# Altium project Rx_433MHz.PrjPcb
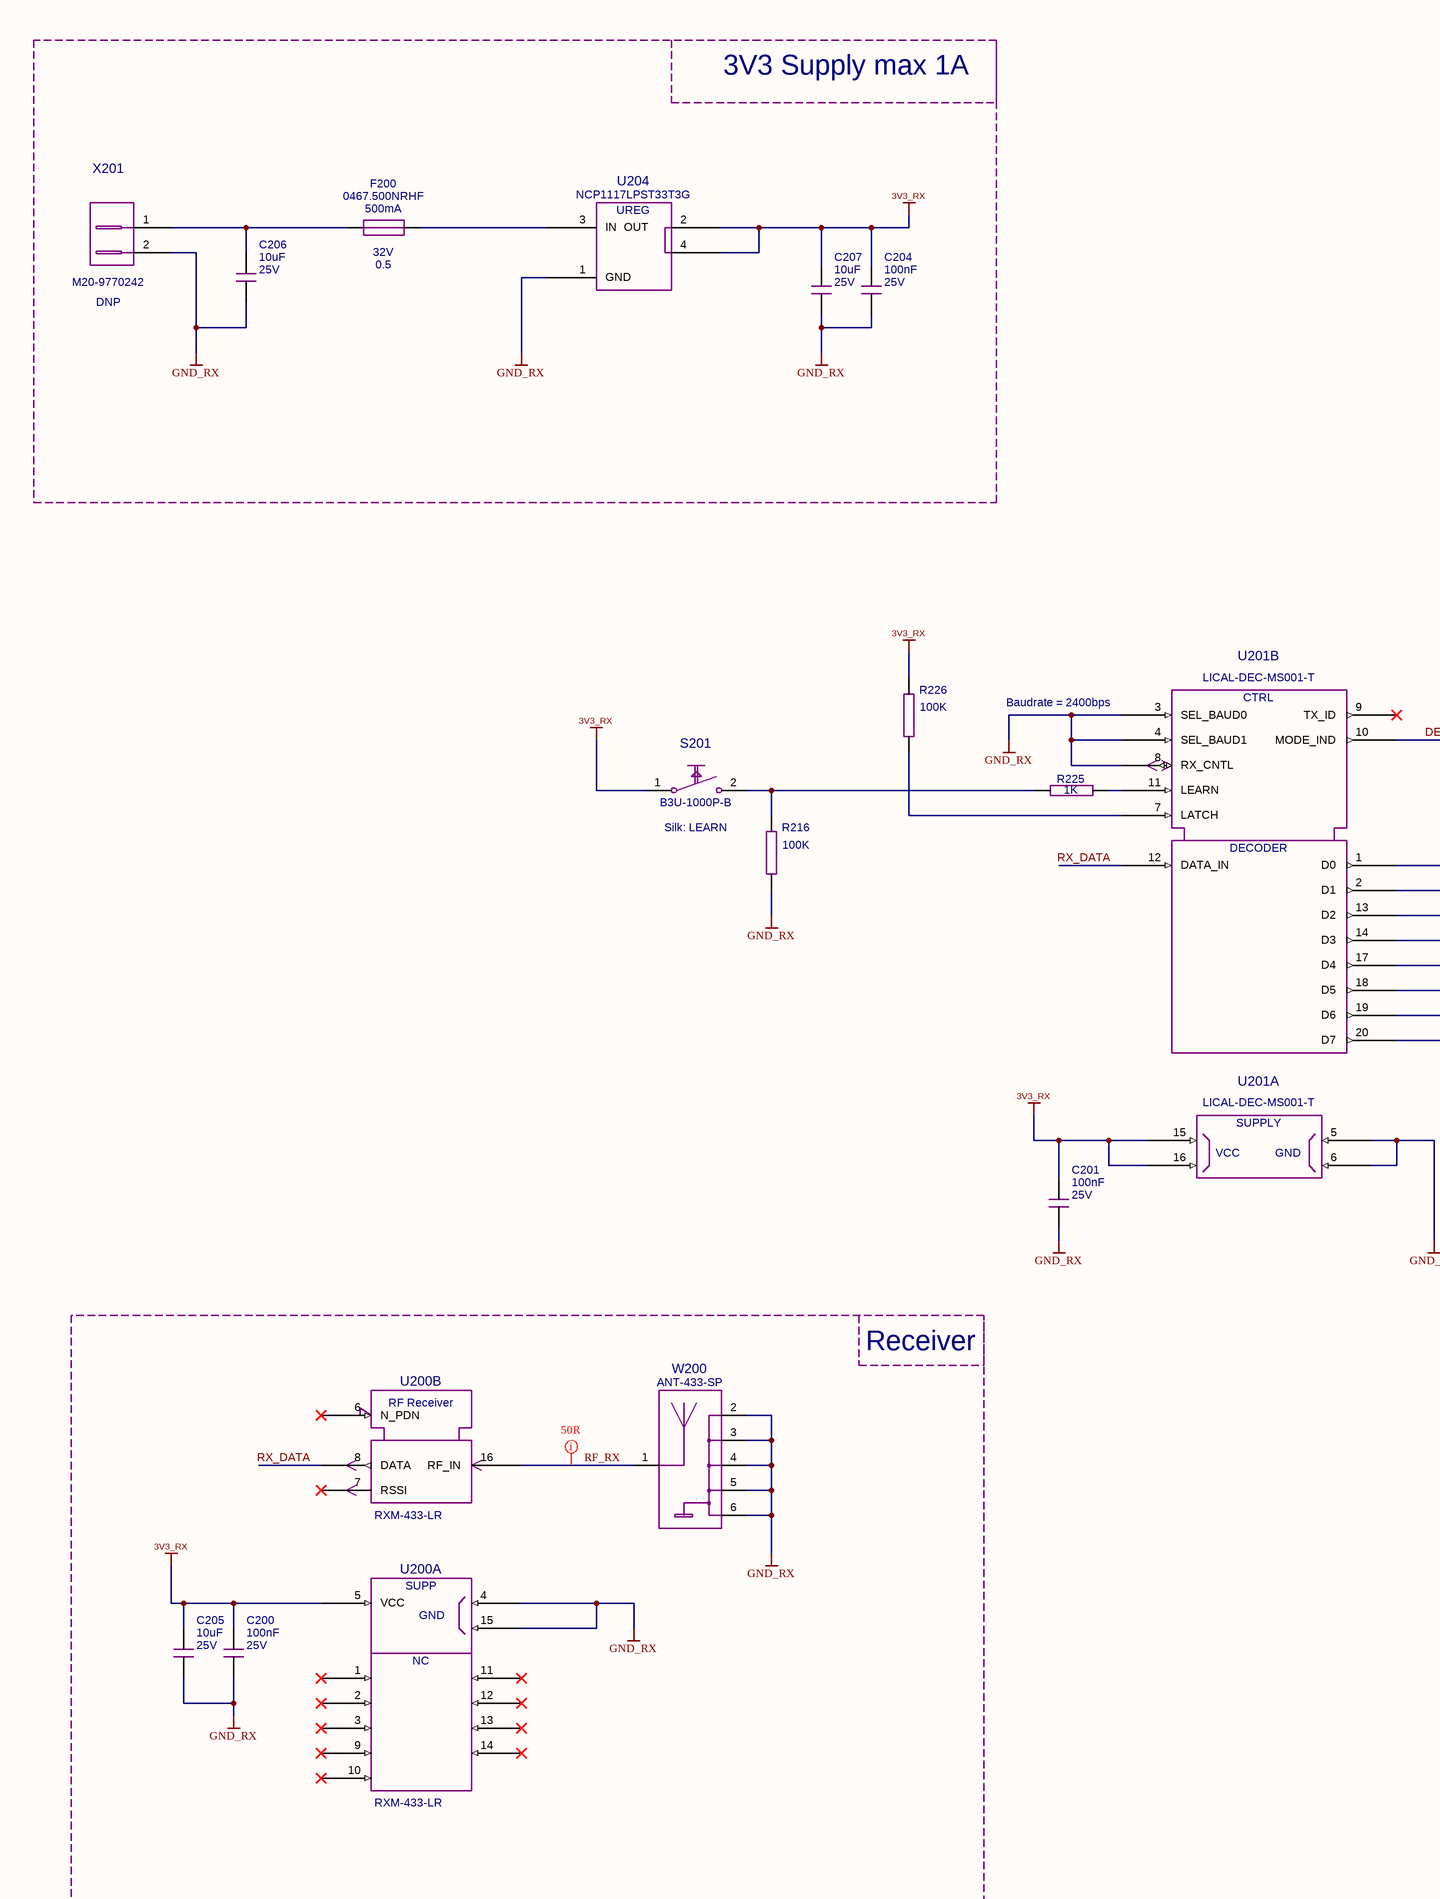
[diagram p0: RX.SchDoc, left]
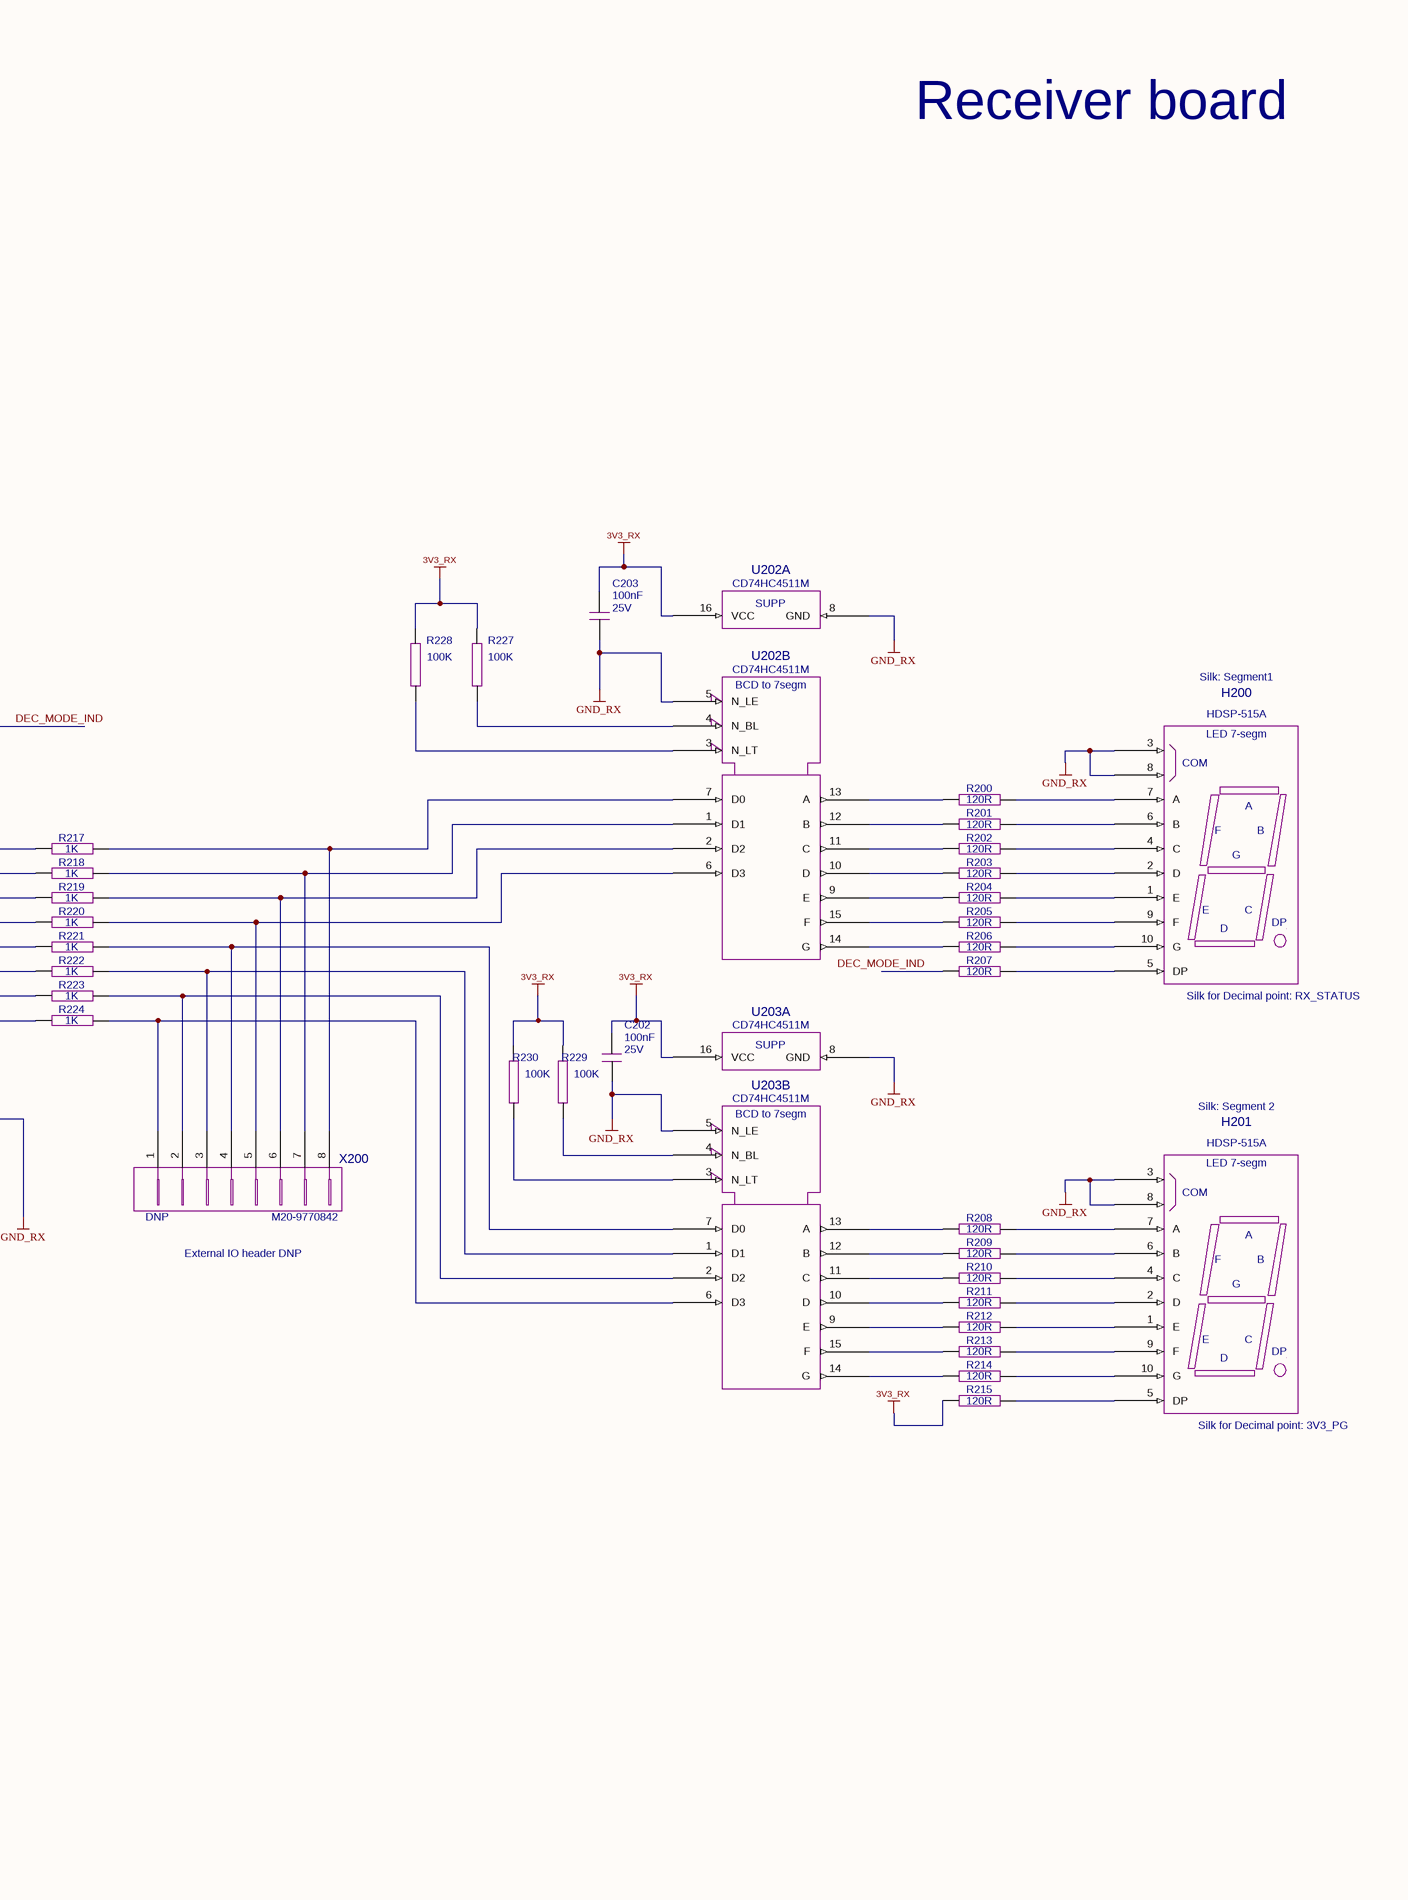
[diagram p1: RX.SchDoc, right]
1 sheet, 51 parts. Net scope: hierarchical (ports join the sheet entries above them; power ports are global).
Board files: Rx_433MHz.PcbDoc, Rx_433MHz-Placed.PcbDoc, Rx_433MHz-Routed.PcbDoc

## Sheet RX.SchDoc
size 594 x 420 mm; APPROVED: Yes; Border_Classification: ?; CmpIndex: 0; ENGINEER: KuRe/SnLe; REVIEWED: Yes; REVISION: 2.0; SymIndex: 1

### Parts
C200  value 100nF  Voltage: 25V  [CAPC1608X90N_0603_GENERIC]  (hidden comment: C_0603_1608X90_GENERIC)
C201  value 100nF  Voltage: 25V  [CAPC1608X90N_0603_GENERIC]  (hidden comment: C_0603_1608X90_GENERIC)
C202  value 100nF  Voltage: 25V  [CAPC1608X90N_0603_GENERIC]  (hidden comment: C_0603_1608X90_GENERIC)
C203  value 100nF  Voltage: 25V  [CAPC1608X90N_0603_GENERIC]  (hidden comment: C_0603_1608X90_GENERIC)
C204  value 100nF  Voltage: 25V  [CAPC1608X90N_0603_GENERIC]  (hidden comment: C_0603_1608X90_GENERIC)
C205  value 10uF  Voltage: 25V  [CAPC3216X190N_1206_GENERIC]  (hidden comment: C_1206_3216X190_GENERIC)
C206  value 10uF  Voltage: 25V  [CAPC2013X140N_AVX]  (hidden comment: 08051C104KAZ2A)
C207  value 10uF  Voltage: 25V  [CAPC2013X140N_AVX]  (hidden comment: 08051C104KAZ2A)
F200  value 500mA  Current: 0.5  MPN: 0467.500NRHF  Voltage: 32V  [RESC1608X60N_0603_GENERIC]  (hidden comment: 0467XXXX)
H200  MPN: HDSP-515A  [BROADCOM_HDSP-5XXX]  (hidden comment: HDSP-5XXX)
H201  MPN: HDSP-515A  [BROADCOM_HDSP-5XXX]  (hidden comment: HDSP-5XXX)
R200  value 120R  [RESC2012X60N_0805_GENERIC]  (hidden comment: R_0805_2012X60_GENERIC)
R201  value 120R  [RESC2012X60N_0805_GENERIC]  (hidden comment: R_0805_2012X60_GENERIC)
R202  value 120R  [RESC2012X60N_0805_GENERIC]  (hidden comment: R_0805_2012X60_GENERIC)
R203  value 120R  [RESC2012X60N_0805_GENERIC]  (hidden comment: R_0805_2012X60_GENERIC)
R204  value 120R  [RESC2012X60N_0805_GENERIC]  (hidden comment: R_0805_2012X60_GENERIC)
R205  value 120R  [RESC2012X60N_0805_GENERIC]  (hidden comment: R_0805_2012X60_GENERIC)
R206  value 120R  [RESC2012X60N_0805_GENERIC]  (hidden comment: R_0805_2012X60_GENERIC)
R207  value 120R  [RESC2012X60N_0805_GENERIC]  (hidden comment: R_0805_2012X60_GENERIC)
R208  value 120R  [RESC2012X60N_0805_GENERIC]  (hidden comment: R_0805_2012X60_GENERIC)
R209  value 120R  [RESC2012X60N_0805_GENERIC]  (hidden comment: R_0805_2012X60_GENERIC)
R210  value 120R  [RESC2012X60N_0805_GENERIC]  (hidden comment: R_0805_2012X60_GENERIC)
R211  value 120R  [RESC2012X60N_0805_GENERIC]  (hidden comment: R_0805_2012X60_GENERIC)
R212  value 120R  [RESC2012X60N_0805_GENERIC]  (hidden comment: R_0805_2012X60_GENERIC)
R213  value 120R  [RESC2012X60N_0805_GENERIC]  (hidden comment: R_0805_2012X60_GENERIC)
R214  value 120R  [RESC2012X60N_0805_GENERIC]  (hidden comment: R_0805_2012X60_GENERIC)
R215  value 120R  [RESC2012X60N_0805_GENERIC]  (hidden comment: R_0805_2012X60_GENERIC)
R216  value 100K  [RESC2012X60N_0805_GENERIC]  (hidden comment: R_0805_2012X60_GENERIC)
R217  value 1K  [RESC2012X60N_0805_GENERIC]  (hidden comment: R_0805_2012X60_GENERIC)
R218  value 1K  [RESC2012X60N_0805_GENERIC]  (hidden comment: R_0805_2012X60_GENERIC)
R219  value 1K  [RESC2012X60N_0805_GENERIC]  (hidden comment: R_0805_2012X60_GENERIC)
R220  value 1K  [RESC2012X60N_0805_GENERIC]  (hidden comment: R_0805_2012X60_GENERIC)
R221  value 1K  [RESC2012X60N_0805_GENERIC]  (hidden comment: R_0805_2012X60_GENERIC)
R222  value 1K  [RESC2012X60N_0805_GENERIC]  (hidden comment: R_0805_2012X60_GENERIC)
R223  value 1K  [RESC2012X60N_0805_GENERIC]  (hidden comment: R_0805_2012X60_GENERIC)
R224  value 1K  [RESC2012X60N_0805_GENERIC]  (hidden comment: R_0805_2012X60_GENERIC)
R225  value 1K  [RESC2012X60N_0805_GENERIC]  (hidden comment: R_0805_2012X60_GENERIC)
R226  value 100K  [RESC2012X60N_0805_GENERIC]  (hidden comment: R_0805_2012X60_GENERIC)
R227  value 100K  [RESC2012X60N_0805_GENERIC]  (hidden comment: R_0805_2012X60_GENERIC)
R228  value 100K  [RESC2012X60N_0805_GENERIC]  (hidden comment: R_0805_2012X60_GENERIC)
R229  value 100K  [RESC2012X60N_0805_GENERIC]  (hidden comment: R_0805_2012X60_GENERIC)
R230  value 100K  [RESC2012X60N_0805_GENERIC]  (hidden comment: R_0805_2012X60_GENERIC)
S201  MPN: B3U-1000P-B  [OMRON_B3U_1000P_B]  (hidden comment: B3U_1000P_B)
U200  RXM-433-LR  [LINX_RXM-433-LR]  (parts A,B of 2)
U201  MPN: LICAL-DEC-MS001-T  [SOP65P780X200-20N]  (hidden comment: LICAL-DEC-MS001)  (parts A,B of 2)
U202  CD74HC4511M  [SOIC127P600X175-16N]  (parts A,B of 2)
U203  CD74HC4511M  [SOIC127P600X175-16N]  (parts A,B of 2)
U204  MPN: NCP1117LPST33T3G  [SOT230P700X180-4N]  (hidden comment: LM1117MPX)
W200  ANT-433-SP  [LINX_ANT-433-SP]
X200  MPN: M20-9770842  Place: DNP  [HARWIN_M20_9770842]  (hidden comment: M20_9770842)
X201  MPN: M20-9770242  Place: DNP  [HARWIN_M20_9770242]  (hidden comment: M20_9770242)

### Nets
3V3_RX: C200.1(P) C201.1(P) C202.1(P) C203.1(P) C204.1(P) C205.1(P) C207.1(P) R215.1(P) R226.2(M) R227.2(M) R228.2(M) R229.2(M) R230.2(M) S201.1(S1) U200.5(VCC) U201.15(VCC1) U201.16(VCC2) U202.16(VCC) U203.16(VCC) U204.2(OUT) U204.4(TAB)
GND_RX: C200.2(M) C201.2(M) C202.2(M) C203.2(M) C204.2(M) C205.2(M) C206.2(M) C207.2(M) H200.3(COM1) H200.8(COM2) H201.3(COM1) H201.8(COM2) R216.1(P) U200.4(GND1) U200.15(GND2) U201.3(SEL_BAUD0) U201.4(SEL_BAUD1) U201.5(GND1) U201.6(GND2) U201.8(RX_CNTL) U202.5(N_LE) U202.8(GND) U203.5(N_LE) U203.8(GND) U204.1(GND) W200.2(GND1) W200.3(GND2) W200.4(GND3) W200.5(GND4) W200.6(GND5) X201.2(P2)
DEC_MODE_IND: R207.1(P) U201.10(MODE_IND)
RF_RX: U200.16(RF_IN) W200.1(ANT)
RX_DATA: U200.8(DATA) U201.12(DATA_IN)
NetC206_1: C206.1(P) F200.1(A) X201.1(P1)
NetF200_2: F200.2(B) U204.3(IN)
NetH200_1: H200.1(E) R204.2(M)
NetH200_2: H200.2(D) R203.2(M)
NetH200_4: H200.4(C) R202.2(M)
NetH200_5: H200.5(DP) R207.2(M)
NetH200_6: H200.6(B) R201.2(M)
NetH200_7: H200.7(A) R200.2(M)
NetH200_9: H200.9(F) R205.2(M)
NetH200_10: H200.10(G) R206.2(M)
NetH201_1: H201.1(E) R212.2(M)
NetH201_2: H201.2(D) R211.2(M)
NetH201_4: H201.4(C) R210.2(M)
NetH201_5: H201.5(DP) R215.2(M)
NetH201_6: H201.6(B) R209.2(M)
NetH201_7: H201.7(A) R208.2(M)
NetH201_9: H201.9(F) R213.2(M)
NetH201_10: H201.10(G) R214.2(M)
NetR200_1: R200.1(P) U202.13(A)
NetR201_1: R201.1(P) U202.12(B)
NetR202_1: R202.1(P) U202.11(C)
NetR203_1: R203.1(P) U202.10(D)
NetR204_1: R204.1(P) U202.9(E)
NetR205_1: R205.1(P) U202.15(F)
NetR206_1: R206.1(P) U202.14(G)
NetR208_1: R208.1(P) U203.13(A)
NetR209_1: R209.1(P) U203.12(B)
NetR210_1: R210.1(P) U203.11(C)
NetR211_1: R211.1(P) U203.10(D)
NetR212_1: R212.1(P) U203.9(E)
NetR213_1: R213.1(P) U203.15(F)
NetR214_1: R214.1(P) U203.14(G)
NetR216_2: R216.2(M) R225.1(P) S201.2(S2)
NetR217_1: R217.1(P) U201.1(D0)
NetR217_2: R217.2(M) U202.7(D0) X200.8(P8)
NetR218_1: R218.1(P) U201.2(D1)
NetR218_2: R218.2(M) U202.1(D1) X200.7(P7)
NetR219_1: R219.1(P) U201.13(D2)
NetR219_2: R219.2(M) U202.2(D2) X200.6(P6)
NetR220_1: R220.1(P) U201.14(D3)
NetR220_2: R220.2(M) U202.6(D3) X200.5(P5)
NetR221_1: R221.1(P) U201.17(D4)
NetR221_2: R221.2(M) U203.7(D0) X200.4(P4)
NetR222_1: R222.1(P) U201.18(D5)
NetR222_2: R222.2(M) U203.1(D1) X200.3(P3)
NetR223_1: R223.1(P) U201.19(D6)
NetR223_2: R223.2(M) U203.2(D2) X200.2(P2)
NetR224_1: R224.1(P) U201.20(D7)
NetR224_2: R224.2(M) U203.6(D3) X200.1(P1)
NetR225_2: R225.2(M) U201.11(LEARN)
NetR226_1: R226.1(P) U201.7(LATCH)
NetR227_1: R227.1(P) U202.4(N_BL)
NetR228_1: R228.1(P) U202.3(N_LT)
NetR229_1: R229.1(P) U203.4(N_BL)
NetR230_1: R230.1(P) U203.3(N_LT)

Not connected (* = marked no-connect by the designer): U200 1(NC1)* 2(NC2)* 3(NC3)* 6(N_PDN)* 7(RSSI)* 9(NC4)* 10(NC5)* 11(NC6)* 12(NC7)* 13(NC8)* 14(NC9)*; U201 9(TX_ID)*

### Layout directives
net class 50R: RF_RX

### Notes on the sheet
- 3V3 Supply max 1A
- Receiver board
- Baudrate = 2400bps
- Silk: Segment1
- Silk: LEARN
- (near H200) Silk for Decimal point: RX_STATUS
- Silk: Segment 2
- External IO header DNP
- Receiver
- (near H201) Silk for Decimal point: 3V3_PG

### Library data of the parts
C200 = C_0603_1608X90_GENERIC: 100nF 25V 10%; Manufacturer: MURATA; MPN: GRM188R71E104KA01D; Part Name: Ceramic chip capacitor 0603-1608x90, generic; Parts: 1; Capacitance: 100000; CmpIndex: 30; Dielectric: X7R; DXDB_LIBNAME: Capacitor; Level: STD; Ref Designator: C200; SymIndex: 23; Tolerance: 10; Type: Ceramic; Valid: -1
C201 = C_0603_1608X90_GENERIC: 100nF 25V 10%; Manufacturer: MURATA; MPN: GRM188R71E104KA01D; Part Name: Ceramic chip capacitor 0603-1608x90, generic; Parts: 1; Capacitance: 100000; CmpIndex: 52; Dielectric: X7R; DXDB_LIBNAME: Capacitor; Level: STD; Ref Designator: C201; SymIndex: 23; Tolerance: 10; Type: Ceramic; Valid: -1
C202 = C_0603_1608X90_GENERIC: 100nF 25V 10%; Manufacturer: MURATA; MPN: GRM188R71E104KA01D; Part Name: Ceramic chip capacitor 0603-1608x90, generic; Parts: 1; Capacitance: 100000; CmpIndex: 80; Dielectric: X7R; DXDB_LIBNAME: Capacitor; Level: STD; Ref Designator: C202; SymIndex: 23; Tolerance: 10; Type: Ceramic; Valid: -1
C203 = C_0603_1608X90_GENERIC: 100nF 25V 10%; Manufacturer: MURATA; MPN: GRM188R71E104KA01D; Part Name: Ceramic chip capacitor 0603-1608x90, generic; Parts: 1; Capacitance: 100000; CmpIndex: 81; Dielectric: X7R; DXDB_LIBNAME: Capacitor; Level: STD; Ref Designator: C203; SymIndex: 23; Tolerance: 10; Type: Ceramic; Valid: -1
C204 = C_0603_1608X90_GENERIC: 100nF 25V 10%; Manufacturer: MURATA; MPN: GRM188R71E104KA01D; Part Name: Ceramic chip capacitor 0603-1608x90, generic; Parts: 1; Capacitance: 100000; CmpIndex: 16; Dielectric: X7R; DXDB_LIBNAME: Capacitor; Level: STD; Ref Designator: C204; SymIndex: 23; Tolerance: 10; Type: Ceramic; Valid: -1
C205 = C_1206_3216X190_GENERIC: 10uF 25V 10%; Manufacturer: AVX; MPN: 12063C106KAT2A; Part Name: Cheramic chip capacitor 1206-3216x190, generic; Parts: 1; Capacitance: 10000000; CmpIndex: 33; Dielectric: X7R; DXDB_LIBNAME: Capacitor; Level: STD; Max Temp: +125; Min Temp: -55; Ref Designator: C205; SymIndex: 23; Tolerance: 10; Type: Ceramic; Valid: -1
C206 = 08051C104KAZ2A: 10uF 25V 10%; Manufacturer: AVX; MPN: 08053D106KAT2A; Part Name: 0805 chip 100nF 10% 100V X7R; Parts: 1; Capacitance: 10000000; CmpIndex: 12; Dielectric: X5R; DXDB_LIBNAME: Capacitor; Level: STD; Ref Designator: C206; SymIndex: 23; Tolerance: 10; Type: Ceramic; Valid: 0
C207 = 08051C104KAZ2A: 10uF 25V 10%; Manufacturer: AVX; MPN: 08053D106KAT2A; Part Name: 0805 chip 100nF 10% 100V X7R; Parts: 1; Capacitance: 10000000; CmpIndex: 15; Dielectric: X5R; DXDB_LIBNAME: Capacitor; Level: STD; Ref Designator: C207; SymIndex: 23; Tolerance: 10; Type: Ceramic; Valid: 0
F200 = 0467XXXX: Thin film 0603 fuse very fast acting; Manufacturer: LITTELFUSE; Part Name: Thin film 0603 very fast acting; CmpIndex: 18; Level: STD; Max Temp: +90; Min Temp: -55; Ref Designator: F200; SymIndex: 25; Valid: -1
H200 = HDSP-5XXX: 7 Segment Display Module Red, 1,85V, 20mA. THT; Manufacturer: BROADCOM; Part Name: Single Digit LED Numeric Display, Blue color; CmpIndex: 5; DXDB_LIBNAME: Optical; Level: STD; Max Temp: 85; Min Temp: -25; Ref Designator: H200; SymIndex: 14; Valid: 0
H201 = HDSP-5XXX: 7 Segment Display Module Red, 1,85V, 20mA. THT; Manufacturer: BROADCOM; Part Name: Single Digit LED Numeric Display, Blue color; CmpIndex: 66; DXDB_LIBNAME: Optical; Level: STD; Max Temp: 85; Min Temp: -25; Ref Designator: H201; SymIndex: 14; Valid: 0
R200 = R_0805_2012X60_GENERIC: 0.125W 5% 120R 50V; Manufacturer: YAGEO; MPN: RC0805JR-07120RL; Part Name: resistor_0805-2012x60 generic; CmpIndex: 40; DXDB_LIBNAME: Resistor_0805; Level: STD; Ref Designator: R200; SymIndex: 28; Valid: -1
R201 = R_0805_2012X60_GENERIC: 0.125W 5% 120R 50V; Manufacturer: YAGEO; MPN: RC0805JR-07120RL; Part Name: resistor_0805-2012x60 generic; CmpIndex: 41; DXDB_LIBNAME: Resistor_0805; Level: STD; Ref Designator: R201; SymIndex: 28; Valid: -1
R202 = R_0805_2012X60_GENERIC: 0.125W 5% 120R 50V; Manufacturer: YAGEO; MPN: RC0805JR-07120RL; Part Name: resistor_0805-2012x60 generic; CmpIndex: 60; DXDB_LIBNAME: Resistor_0805; Level: STD; Ref Designator: R202; SymIndex: 28; Valid: -1
R203 = R_0805_2012X60_GENERIC: 0.125W 5% 120R 50V; Manufacturer: YAGEO; MPN: RC0805JR-07120RL; Part Name: resistor_0805-2012x60 generic; CmpIndex: 61; DXDB_LIBNAME: Resistor_0805; Level: STD; Ref Designator: R203; SymIndex: 28; Valid: -1
R204 = R_0805_2012X60_GENERIC: 0.125W 5% 120R 50V; Manufacturer: YAGEO; MPN: RC0805JR-07120RL; Part Name: resistor_0805-2012x60 generic; CmpIndex: 62; DXDB_LIBNAME: Resistor_0805; Level: STD; Ref Designator: R204; SymIndex: 28; Valid: -1
R205 = R_0805_2012X60_GENERIC: 0.125W 5% 120R 50V; Manufacturer: YAGEO; MPN: RC0805JR-07120RL; Part Name: resistor_0805-2012x60 generic; CmpIndex: 63; DXDB_LIBNAME: Resistor_0805; Level: STD; Ref Designator: R205; SymIndex: 28; Valid: -1
R206 = R_0805_2012X60_GENERIC: 0.125W 5% 120R 50V; Manufacturer: YAGEO; MPN: RC0805JR-07120RL; Part Name: resistor_0805-2012x60 generic; CmpIndex: 64; DXDB_LIBNAME: Resistor_0805; Level: STD; Ref Designator: R206; SymIndex: 28; Valid: -1
R207 = R_0805_2012X60_GENERIC: 0.125W 5% 120R 50V; Manufacturer: YAGEO; MPN: RC0805JR-07120RL; Part Name: resistor_0805-2012x60 generic; CmpIndex: 73; DXDB_LIBNAME: Resistor_0805; Level: STD; Ref Designator: R207; SymIndex: 28; Valid: -1
R208 = R_0805_2012X60_GENERIC: 0.125W 5% 120R 50V; Manufacturer: YAGEO; MPN: RC0805JR-07120RL; Part Name: resistor_0805-2012x60 generic; CmpIndex: 6; DXDB_LIBNAME: Resistor_0805; Level: STD; Ref Designator: R208; SymIndex: 28; Valid: -1
R209 = R_0805_2012X60_GENERIC: 0.125W 5% 120R 50V; Manufacturer: YAGEO; MPN: RC0805JR-07120RL; Part Name: resistor_0805-2012x60 generic; CmpIndex: 67; DXDB_LIBNAME: Resistor_0805; Level: STD; Ref Designator: R209; SymIndex: 28; Valid: -1
R210 = R_0805_2012X60_GENERIC: 0.125W 5% 120R 50V; Manufacturer: YAGEO; MPN: RC0805JR-07120RL; Part Name: resistor_0805-2012x60 generic; CmpIndex: 68; DXDB_LIBNAME: Resistor_0805; Level: STD; Ref Designator: R210; SymIndex: 28; Valid: -1
R211 = R_0805_2012X60_GENERIC: 0.125W 5% 120R 50V; Manufacturer: YAGEO; MPN: RC0805JR-07120RL; Part Name: resistor_0805-2012x60 generic; CmpIndex: 69; DXDB_LIBNAME: Resistor_0805; Level: STD; Ref Designator: R211; SymIndex: 28; Valid: -1
R212 = R_0805_2012X60_GENERIC: 0.125W 5% 120R 50V; Manufacturer: YAGEO; MPN: RC0805JR-07120RL; Part Name: resistor_0805-2012x60 generic; CmpIndex: 70; DXDB_LIBNAME: Resistor_0805; Level: STD; Ref Designator: R212; SymIndex: 28; Valid: -1
R213 = R_0805_2012X60_GENERIC: 0.125W 5% 120R 50V; Manufacturer: YAGEO; MPN: RC0805JR-07120RL; Part Name: resistor_0805-2012x60 generic; CmpIndex: 71; DXDB_LIBNAME: Resistor_0805; Level: STD; Ref Designator: R213; SymIndex: 28; Valid: -1
R214 = R_0805_2012X60_GENERIC: 0.125W 5% 120R 50V; Manufacturer: YAGEO; MPN: RC0805JR-07120RL; Part Name: resistor_0805-2012x60 generic; CmpIndex: 72; DXDB_LIBNAME: Resistor_0805; Level: STD; Ref Designator: R214; SymIndex: 28; Valid: -1
R215 = R_0805_2012X60_GENERIC: 0.125W 5% 120R 50V; Manufacturer: YAGEO; MPN: RC0805JR-07120RL; Part Name: resistor_0805-2012x60 generic; CmpIndex: 74; DXDB_LIBNAME: Resistor_0805; Level: STD; Ref Designator: R215; SymIndex: 28; Valid: -1
R216 = R_0805_2012X60_GENERIC: 0.125W 5% 100K 50V; Manufacturer: YAGEO; MPN: RC0805JR-07100KL; Part Name: resistor_0805-2012x60 generic; CmpIndex: 38; DXDB_LIBNAME: Resistor_0805; Level: STD; Ref Designator: R216; SymIndex: 28; Valid: -1
R217 = R_0805_2012X60_GENERIC: Resistor_1K_1%_0805; Manufacturer: MULTICOMP; MPN: MCPWR05FTEW1001; Part Name: resistor_0805-2012x60 generic; CmpIndex: 43; DXDB_LIBNAME: Resistor_0805; Level: STD; Ref Designator: R217; SymIndex: 28; Tolerance: 1%; Valid: -1
R218 = R_0805_2012X60_GENERIC: Resistor_1K_1%_0805; Manufacturer: MULTICOMP; MPN: MCPWR05FTEW1001; Part Name: resistor_0805-2012x60 generic; CmpIndex: 44; DXDB_LIBNAME: Resistor_0805; Level: STD; Ref Designator: R218; SymIndex: 28; Tolerance: 1%; Valid: -1
R219 = R_0805_2012X60_GENERIC: Resistor_1K_1%_0805; Manufacturer: MULTICOMP; MPN: MCPWR05FTEW1001; Part Name: resistor_0805-2012x60 generic; CmpIndex: 45; DXDB_LIBNAME: Resistor_0805; Level: STD; Ref Designator: R219; SymIndex: 28; Tolerance: 1%; Valid: -1
R220 = R_0805_2012X60_GENERIC: Resistor_1K_1%_0805; Manufacturer: MULTICOMP; MPN: MCPWR05FTEW1001; Part Name: resistor_0805-2012x60 generic; CmpIndex: 46; DXDB_LIBNAME: Resistor_0805; Level: STD; Ref Designator: R220; SymIndex: 28; Tolerance: 1%; Valid: -1
R221 = R_0805_2012X60_GENERIC: Resistor_1K_1%_0805; Manufacturer: MULTICOMP; MPN: MCPWR05FTEW1001; Part Name: resistor_0805-2012x60 generic; CmpIndex: 47; DXDB_LIBNAME: Resistor_0805; Level: STD; Ref Designator: R221; SymIndex: 28; Tolerance: 1%; Valid: -1
R222 = R_0805_2012X60_GENERIC: Resistor_1K_1%_0805; Manufacturer: MULTICOMP; MPN: MCPWR05FTEW1001; Part Name: resistor_0805-2012x60 generic; CmpIndex: 48; DXDB_LIBNAME: Resistor_0805; Level: STD; Ref Designator: R222; SymIndex: 28; Tolerance: 1%; Valid: -1
R223 = R_0805_2012X60_GENERIC: Resistor_1K_1%_0805; Manufacturer: MULTICOMP; MPN: MCPWR05FTEW1001; Part Name: resistor_0805-2012x60 generic; CmpIndex: 49; DXDB_LIBNAME: Resistor_0805; Level: STD; Ref Designator: R223; SymIndex: 28; Tolerance: 1%; Valid: -1
R224 = R_0805_2012X60_GENERIC: Resistor_1K_1%_0805; Manufacturer: MULTICOMP; MPN: MCPWR05FTEW1001; Part Name: resistor_0805-2012x60 generic; CmpIndex: 50; DXDB_LIBNAME: Resistor_0805; Level: STD; Ref Designator: R224; SymIndex: 28; Tolerance: 1%; Valid: -1
R225 = R_0805_2012X60_GENERIC: Resistor_1K_1%_0805; Manufacturer: MULTICOMP; MPN: MCPWR05FTEW1001; Part Name: resistor_0805-2012x60 generic; CmpIndex: 35; DXDB_LIBNAME: Resistor_0805; Level: STD; Ref Designator: R225; SymIndex: 28; Tolerance: 1%; Valid: -1
R226 = R_0805_2012X60_GENERIC: 0.125W 5% 100K 50V; Manufacturer: YAGEO; MPN: RC0805JR-07100KL; Part Name: resistor_0805-2012x60 generic; CmpIndex: 57; DXDB_LIBNAME: Resistor_0805; Level: STD; Ref Designator: R226; SymIndex: 28; Valid: -1
R227 = R_0805_2012X60_GENERIC: 0.125W 5% 100K 50V; Manufacturer: YAGEO; MPN: RC0805JR-07100KL; Part Name: resistor_0805-2012x60 generic; CmpIndex: 86; DXDB_LIBNAME: Resistor_0805; Level: STD; Ref Designator: R227; SymIndex: 28; Valid: -1
R228 = R_0805_2012X60_GENERIC: 0.125W 5% 100K 50V; Manufacturer: YAGEO; MPN: RC0805JR-07100KL; Part Name: resistor_0805-2012x60 generic; CmpIndex: 87; DXDB_LIBNAME: Resistor_0805; Level: STD; Ref Designator: R228; SymIndex: 28; Valid: -1
R229 = R_0805_2012X60_GENERIC: 0.125W 5% 100K 50V; Manufacturer: YAGEO; MPN: RC0805JR-07100KL; Part Name: resistor_0805-2012x60 generic; CmpIndex: 89; DXDB_LIBNAME: Resistor_0805; Level: STD; Ref Designator: R229; SymIndex: 28; Valid: -1
R230 = R_0805_2012X60_GENERIC: 0.125W 5% 100K 50V; Manufacturer: YAGEO; MPN: RC0805JR-07100KL; Part Name: resistor_0805-2012x60 generic; CmpIndex: 91; DXDB_LIBNAME: Resistor_0805; Level: STD; Ref Designator: R230; SymIndex: 28; Valid: -1
S201 = B3U_1000P_B: Ultra-small Tactile Switch; Manufacturer: OMRON; CmpIndex: 1; Contacts: 2; Level: STD; Max Temp: 0; Ref Designator: S201; SymIndex: 8
U200 = RXM-433-LR: LR Series Receiver, Low Voltage, Low Power; Manufacturer: Linx Technologies; CmpIndex: 4; DXDB_LIBNAME: Module; Level: STD; Max Temp: 70; Min Temp: -40; Quality: Q2; Ref Designator: U200; SymIndex: 13; Valid: 0
U201 = LICAL-DEC-MS001: MS Series Remote Controler Decoder, Low Voltage, Low Power; Manufacturer: LINX TECHNOLOGIES; CmpIndex: 8; DXDB_LIBNAME: IC Generic; Level: STD; Max Temp: 85; Min Temp: -40; Ref Designator: U201; SymIndex: 16; Valid: 0
U202 = CD74HC4511M: Leddriver BCD to 7 segment 1 Digit; Manufacturer: TEXAS INSTRUMENTS; Parts: 1; CmpIndex: 55; DXDB_LIBNAME: IC Generic; Level: STD; Max Temp: 125; Min Temp: -55; Ref Designator: U202; SymIndex: 32; Valid: 0
U203 = CD74HC4511M: Leddriver BCD to 7 segment 1 Digit; Manufacturer: TEXAS INSTRUMENTS; Parts: 1; CmpIndex: 75; DXDB_LIBNAME: IC Generic; Level: STD; Max Temp: 125; Min Temp: -55; Ref Designator: U203; SymIndex: 32; Valid: 0
U204 = LM1117MPX: 3.3V/1A fixed regulator; Manufacturer: ON-SEMI; Part Name: 800mA Low-Dropout Linear Regulator, SOT223; CmpIndex: 10; DXDB_LIBNAME: IC Power; Level: STD; Ref Designator: U204; SymIndex: 36; Valid: -1; Vin Max: 18; Vin Min: -0.3; Vout Max: 3.365; Vout Min: 3.235
W200 = ANT-433-SP: 433MHz 50 Ohm Antenna module; Manufacturer: Linx Technologies; CmpIndex: 93; Level: STD; Max Temp: 130; Min Temp: -40; Quality: Q2; Ref Designator: W200; SymIndex: 37; Valid: 0
X200 = M20_9770842: 1x8 pin 2.54 mm pitch vertical header; Manufacturer: HARWIN; Part Name: STD_HEADER_1x8_2.54_THT; CmpIndex: 9; DXDB_LIBNAME: Connector; Gender: male; Level: STD; Ref Designator: X200; SymIndex: 17; Valid: -1
X201 = M20_9770242: 1x2 pin 2.54 mm pitch vertical header; Manufacturer: HARWIN; Part Name: STD_HEADER_1x2_2.54_THT; CmpIndex: 11; DXDB_LIBNAME: Connector; Gender: male; Level: STD; Name: 9V in; Ref Designator: X201; SymIndex: 21; Valid: -1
